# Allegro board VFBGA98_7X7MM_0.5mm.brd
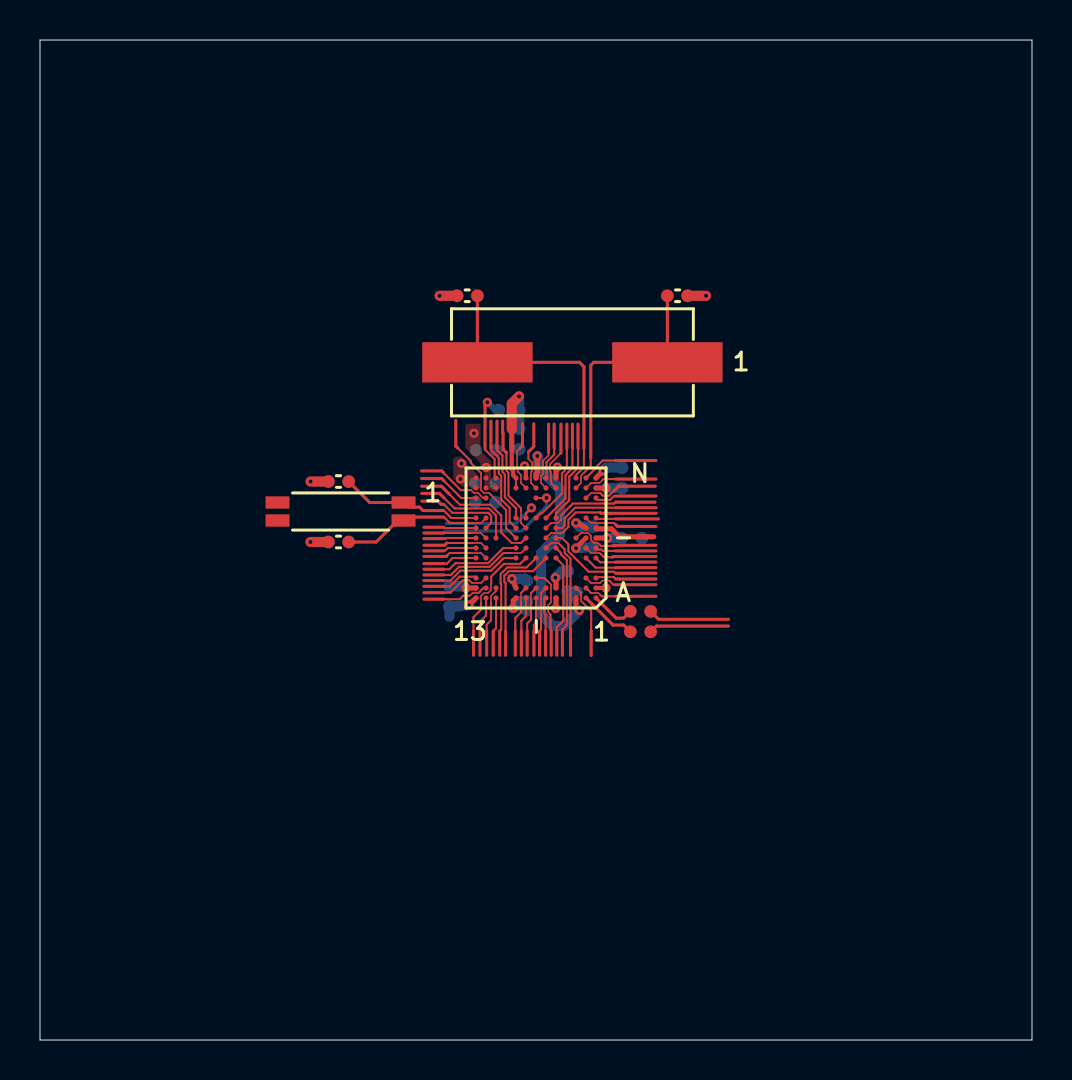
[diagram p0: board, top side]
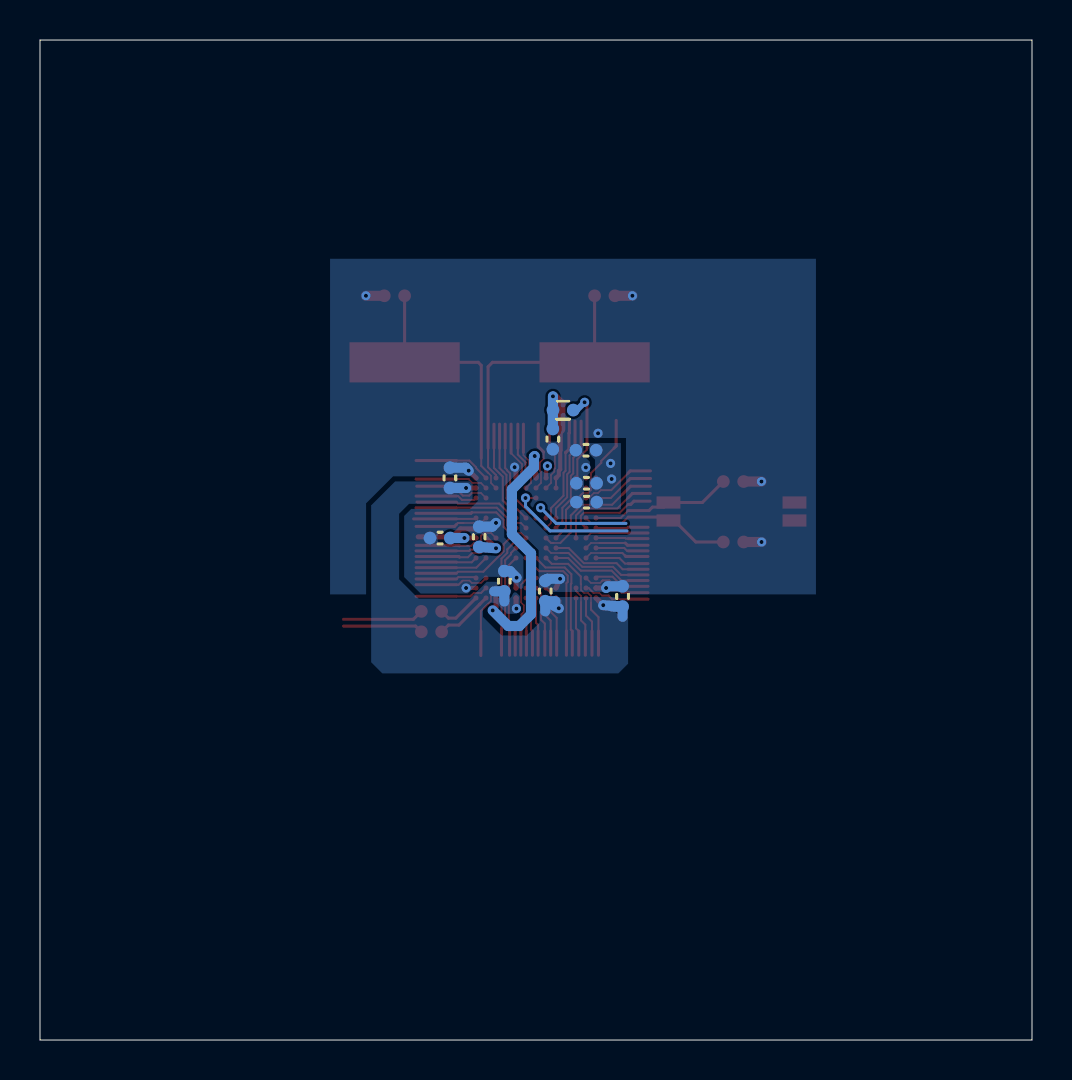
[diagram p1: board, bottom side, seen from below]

Outline 49.6 x 50 mm; copper layers: TOP, BOTTOM. Coordinates in mm from the lower left corner of the outline.
Outline path: 0,50 0,0 49.6,0 49.6,50 0,50

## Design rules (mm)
constraint set DEFAULT: min track width 0.152
net group CSI_LANE: nets P0_13 P0_20 P0_21
net group POWER: nets +3.3V_USB N03445 USB_VBUS VDD3V3_ADC VREFN VREFP

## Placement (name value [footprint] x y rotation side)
C1  22uF  [CC0402_25]  22.28 27.84 0 bottom
C2  0.1UF  [CC0402_25]  22.27 26.89 0 bottom
C3  0.1UF  [CC0402_25]  27.64 25.16 90 bottom
C4  0.1UF  [CC0402_25]  20.47 22.18 90 bottom
C5  4.7UF  [CC0402_25]  24.34 22.45 90 bottom
C6  27PF  [CC0402_25]  21.36 37.21 180 top
C7  0.01UF  [CC0402_25]  29.59 25.1 0 bottom
C8  0.01UF  [CC0402_25]  26.39 22.94 90 bottom
C9  47pF  [CC0402_25]  22.3 29.49 0 bottom
C10  0.1UF  [CC0402_25]  29.1 28.11 90 bottom
C11  27PF  [CC0402_25]  31.88 37.21 0 top
C12  22uF  [CC0402_25]  23.96 30.04 270 bottom
C13  18pF  [CC0402_25]  14.93 27.92 180 top
C14  18pF  [CC0402_25]  14.93 24.9 180 top
L1  33nH  [IND_0402]  23.44 31.5 0 bottom
NOREF  -  []  22.3 28.1 0 top
NOREF#2  -  []  21.3 21.6 90 top
NOREF#3  -  []  -341.81 -256.67 0 top
NOREF#4  -  []  11.88 25.97 90 top
NOREF#5  -  []  25.8 28.1 0 top
NOREF#6  -  []  27.8 28.6 0 top
NOREF#7  -  []  11.88 26.87 0 top
NOREF#8  -  []  21.3 28.6 0 top
NOREF#9  -  []  22.3 28.1 0 top
NOREF#10  -  []  21.8 25.6 90 top
NOREF#11  -  []  276.78 -23.85 0 top
NOREF#12  -  []  91.14 51.78 0 top
NOREF#13  -  []  25.8 28.1 0 top
NOREF#14  -  []  21.3 28.6 0 top
NOREF#15  -  []  21.8 23.1 90 top
NOREF#16  -  []  21.3 21.6 90 top
NOREF#17  -  []  10.89 25.67 90 top
NOREF#18  -  []  21.8 25.6 90 top
NOREF#19  -  []  -58.09 -204.72 0 top
NOREF#20  -  []  278.26 -35.28 90 top
NOREF#21  -  []  -315.77 265.94 0 top
NOREF#22  -  []  21.8 23.1 90 top
NOREF#23  -  []  10.89 27.17 0 top
NOREF#24  -  []  -45.77 -55.12 0 top
R1  33  [RC0402_25]  30.03 20.41 180 top
R2  33  [RC0402_25]  30.03 21.43 180 top
U1  VFBA98_7x7x<1mm_0p5  [BGA98_0P5_7X7X1MM]  24.8 25.1 0 top
Y1  16.000MHZ  [HC49SDLF]  26.62 33.88 180 top
Y2  32.768kHz  [XTAL4_7X1P5_SM]  15.03 26.42 180 top

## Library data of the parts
C1-C14 = CAP_NP
L1 = INDUCTOR
R1 R2 = RES
U1 = VFBA98_7x7x<1mm_0p5
Y1 = XTAL
Y2 = XTAL_14

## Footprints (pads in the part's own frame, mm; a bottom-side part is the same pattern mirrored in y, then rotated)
BGA98_0P5_7X7X1MM
  round 0.254 smd: A1(3,-3) A2(2.5,-3) A3(2,-3) A5(1,-3) A6(0.5,-3) A7(0,-3) A8(-0.5,-3) A9(-1,-3) A11(-2,-3) A12(-2.5,-3) A13(-3,-3) B1(3,-2.5) B2(2.5,-2.5) B3(2,-2.5) B5(1,-2.5) B6(0.5,-2.5) B7(0,-2.5) B8(-0.5,-2.5) B9(-1,-2.5) B11(-2,-2.5) B12(-2.5,-2.5) B13(-3,-2.5) C1(3,-2) C2(2.5,-2) C7(0,-2) C12(-2.5,-2) C13(-3,-2) E1(3,-1) E2(2.5,-1) E5(1,-1) E6(0.5,-1) E7(0,-1) E8(-0.5,-1) E9(-1,-1) E12(-2.5,-1) E13(-3,-1) F1(3,-0.5) F2(2.5,-0.5) F5(1,-0.5) F6(0.5,-0.5) F8(-0.5,-0.5) F9(-1,-0.5) F12(-2.5,-0.5) F13(-3,-0.5) G1(3,0) G2(2.5,0) G3(2,0) G5(1,0) G6(0.5,0) G8(-0.5,0) G9(-1,0) G11(-2,0) G12(-2.5,0) G13(-3,0) H1(3,0.5) H2(2.5,0.5) H5(1,0.5) H6(0.5,0.5) H8(-0.5,0.5) H9(-1,0.5) H12(-2.5,0.5) H13(-3,0.5) J1(3,1) J2(2.5,1) J5(1,1) J6(0.5,1) J7(0,1) J8(-0.5,1) J9(-1,1) J12(-2.5,1) J13(-3,1) L1(3,2) L2(2.5,2) L7(0,2) L12(-2.5,2) L13(-3,2) M1(3,2.5) M2(2.5,2.5) M3(2,2.5) M5(1,2.5) M6(0.5,2.5) M7(0,2.5) M8(-0.5,2.5) M9(-1,2.5) M11(-2,2.5) M12(-2.5,2.5) M13(-3,2.5) N1(3,3) N2(2.5,3) N3(2,3) N5(1,3) N6(0.5,3) N7(0,3) N8(-0.5,3) N9(-1,3) N11(-2,3) N12(-2.5,3) N13(-3,3)
CC0402_25
  round 0.635 smd: 1(-0.508,0) 2(0.508,0)
HC49SDLF
  rect 5.512x2.007 smd: 1(-4.75,0) 2(4.75,0)
IND_0402
  round 0.635 smd: 1(-0.508,0) 2(0.508,0)
RC0402_25
  round 0.635 smd: 1(-0.508,0) 2(0.508,0)
XTAL4_7X1P5_SM
  rect 1.194x0.61 smd: 1(-3.15,-0.45) 2(3.15,-0.45) 3(3.15,0.45) 4(-3.15,0.45)

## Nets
3V3: C4.1 C5.1 C8.1 C10.1 U1.A5 U1.A9 U1.A13 U1.M1
+3.3V_USB: U1.A3 U1.N7
GND: C1.2 C2.2 C3.2 C4.2 C5.2 C6.2 C7.2 C8.2 C9.2 C10.2 C11.2 C12.2 C13.2 C14.2 U1.B1 U1.B5 U1.B9 U1.B13 U1.H2 U1.M11 U1.M12 U1.N1 U1.N5 U1.N12
VBAT: C1.1 C2.1 C9.1 U1.M13 U1.N13
VDD3V3_ADC: C3.1 U1.G2
P0_0: U1.L12
P0_1: U1.F5
P0_2: U1.B11
P0_3: U1.F8
P0_4: U1.E7
P0_5: U1.A7
P0_6: U1.B7
P0_7: U1.G5
P0_8: U1.M2
P0_9: U1.L13
P0_10: U1.F2
P0_11: U1.F1
P0_12: U1.E2
P0_13: U1.C12
P0_14: U1.C13
P0_15: U1.L2
P0_16: U1.J2
P0_17: U1.G3
P0_18: U1.H9
P0_19: U1.E6
P0_20: U1.B12
P0_21: U1.A12
P0_22: U1.E9
P0_23: U1.J1
P0_24: U1.E12
P0_25: U1.A11
P0_26: U1.H12
P0_27: U1.N2
P0_28: U1.F13
P0_29: U1.H8
P0_30: U1.E5
P0_31: U1.L1
P1_0: U1.E1
P1_1: U1.G11
P1_2: U1.G12
P1_3: U1.G13
P1_4: U1.B2
P1_5: U1.M5
P1_6: U1.H5
P1_7: U1.J5
P1_8: U1.A6
P1_9: U1.C1(P1_9)
P1_10: U1.J7
P1_11: U1.G6
P1_12: U1.F12
P1_13: U1.B3
P1_14: U1.L7
P1_15: U1.B6
P1_16: U1.C7
P1_17: U1.J9
P1_18: U1.G9
P1_19: U1.H13
P1_20: U1.C2
P1_21: U1.M7
P1_22: U1.M8
P1_23: U1.J8
P1_24: U1.F6
P1_25: U1.B8
P1_26: U1.E13
P1_27: U1.E8
P1_28: U1.A8
P1_29: U1.G8
P1_30: U1.F9
P1_31: U1.H6
RESET: U1.J6
USB_FS_N: R2.1
USB_FS_P: R1.1
USB_N: U1.N6
USB_P: U1.M6
USB_VBUS: U1.N8
VREFN: U1.H1
VREFP: C7.1 U1.G1
XTAL_RTX_N: C14.1 U1.J12 Y2.4
XTAL_RTX_P: C13.1 U1.J13 Y2.1
N01141: R1.2 U1.A2
N01145: R2.2 U1.A1
N03158: C11.1 U1.M3 Y1.1
N03165: C6.1 U1.N3 Y1.2
N03441: L1.1 U1.N11
N03445: C12.1 L1.2 U1.M9 U1.N9

Pads without a net: Y2 2 3

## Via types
v1: diameter 0.457, hole 0.203, TOP to BOTTOM, 28 vias

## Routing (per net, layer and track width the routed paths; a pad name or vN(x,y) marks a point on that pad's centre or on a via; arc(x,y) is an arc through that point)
3V3: length 7.7
  TOP w0.254: v1(25.78,21.57) 25.8,21.59 25.8,22.1 U1.A5 ; U1.A13 v1(21.44,21.74) ; U1.M1 v1(28.3,27.6) ; v1(23.66,21.58) 23.66,21.96 U1.A9
  BOTTOM w0.508: C5.1 v1(23.66,21.58) ; C5.1 24.34,21.43 ; C5.1 23.83,21.94 ; 20.47,21.16 C4.1 ; C4.1 v1(21.44,21.74) ; C4.1 20.98,21.67 ; C10.1 v1(28.3,27.6) ; 26.89,22.43 C8.1 26.39,21.92
+3.3V_USB: length 13.1
  TOP w0.254: v1(26.96,21.48) 26.8,21.64 U1.A3 ; U1.N7 24.8,28.17 24.8,28.17 24.8,28.31 24.87,28.37 v1(24.87,29.2)
  BOTTOM w0.508: v1(26.96,21.48) 26.19,20.7 25.63,20.7 25.05,21.29 25.05,24.33 26.01,25.29 26.01,27.53 24.9,28.63 24.9,29.16 v1(24.87,29.2)
GND: length 11.6
  TOP w0.203: U1.B1 28.02,22.6 28.02,22.6 v1(28.3,22.6)
  TOP w0.254: U1.B9 v1(23.6,23.06) ; v1(26.8,25.85) 26.85,25.85 U1.H2 ; v1(25.87,28.64) 25.8,28.57 U1.N5 ; v1(21.3,22.6) U1.B13 ; U1.B5 25.8,23.08 v1(25.77,23.11) ; U1.N1 v1(28.17,28.47)
  TOP w0.508: C6.2 v1(19.98,37.21) ; C14.2 v1(13.52,24.9) ; C13.2 v1(13.53,27.92) ; C11.2 v1(33.3,37.21)
  BOTTOM w0.508: v1(25.77,23.11) 26.1,23.45 C8.2 ; v1(28.17,28.47) 28.32,28.62 C10.2 ; C3.2 26.99,25.67 v1(26.8,25.85) ; v1(21.3,22.6) 21.21,22.69 C4.2 ; C5.2 24.23,23.06 v1(23.6,23.06)
  vias: v1(21.7,30.33) v1(22.31,28.63)
VBAT:
  vias: v1(21.07,28.83) v1(21.02,28.05)
VDD3V3_ADC: length 1.6
  TOP w0.229: v1(26.8,24.59) 26.8,24.63 U1.G2
  BOTTOM w0.508: C3.1 v1(26.8,24.59)
P0_0: length 3.8
  TOP w0.081: U1.L12 22.15,27.1 21.9,27.35 21.7,27.35 21.56,27.49
  TOP w0.102: 21.56,27.49 21.04,27.49 20.19,28.34 20.19,28.35
  TOP w0.152: 19.08,28.46 20.09,28.46 20.19,28.35
P0_1: length 5.7
  TOP w0.102: U1.F5 26.05,24.35 26.05,24.28 26.34,23.99 26.34,20.75 26.12,20.53 26.12,20.45
  TOP w0.152: 26.12,20.45 26.12,19.24
P0_2: length 3.6
  TOP w0.081: 22.55,21.89 22.55,22.2 22.71,22.36
  TOP w0.102: 22.33,20.45 22.33,20.77 22.55,20.98 22.55,21.89 ; U1.B11 22.8,22.45 22.71,22.36
  TOP w0.152: 22.33,19.24 22.33,20.45
P0_3: length 5.7
  TOP w0.081: 23.57,24.35 24.05,24.35 U1.F8
  TOP w0.102: 20.19,23.25 20.54,23.25 20.95,23.66 22.48,23.66 23.17,24.35 23.57,24.35
  TOP w0.152: 19.2,23.25 20.19,23.25
P0_4: length 6.2
  TOP w0.102: U1.E7 24.32,23.62 23.36,23.62 23.03,23.29 23.03,22.83 23.06,22.8 23.06,20.52 22.99,20.45
  TOP w0.152: 22.99,19.24 22.99,20.45
P0_5: length 2.9
  TOP w0.102: U1.A7 24.8,20.86 24.69,20.76 24.69,20.45
  TOP w0.152: 24.69,19.24 24.69,20.45
P0_6: length 3.5
  TOP w0.081: 24.55,21.82 24.55,22.35
  TOP w0.102: 24.55,22.35 U1.B7 ; 24.36,20.45 24.36,20.82 24.55,21.02 24.55,21.82
  TOP w0.152: 24.36,19.24 24.36,20.45
P0_7: length 5.9
  TOP w0.102: U1.G5 26.1,25.1 26.42,24.79 26.42,24.43 27.43,23.41 28.7,23.41 28.78,23.34
  TOP w0.152: 30.79,23.34 28.78,23.34
P0_8: length 3.7
  TOP w0.081: 28.16,28.04 27.98,27.85 27.55,27.85 U1.M2
  TOP w0.102: 28.78,28.05 28.17,28.05 28.16,28.04
  TOP w0.152: 28.78,28.05 30.79,28.05
P0_9: length 3.1
  TOP w0.102: 20.19,27.97 21.06,27.1 U1.L13
  TOP w0.152: 19.07,28.07 20.09,28.07 20.19,27.97
P0_10: length 3.7
  TOP w0.081: U1.F2 27.55,24.35 27.99,24.35 28.06,24.28
  TOP w0.102: 28.63,24.14 28.2,24.14 28.06,24.28
  TOP w0.152: 28.63,24.14 28.66,24.18 30.79,24.18
P0_11: length 3.1
  TOP w0.102: U1.F1 27.88,24.52 28.08,24.52 28.14,24.45 28.78,24.45
  TOP w0.152: 30.79,24.45 28.78,24.45
P0_12: length 3.7
  TOP w0.102: 28.78,23.62 27.78,23.62 U1.E2
  TOP w0.152: 30.79,23.62 28.78,23.62
P0_13: length 3.5
  TOP w0.081: 21.5,22.95 21.59,22.85 22.05,22.85 U1.C12
  TOP w0.102: 20.19,22.36 20.52,22.36 21.14,22.98 21.47,22.98 21.5,22.95
  TOP w0.152: 19.2,22.36 20.19,22.36
P0_14: length 2.8
  TOP w0.102: 20.19,22.68 20.49,22.68 20.97,23.16 21.74,23.16 U1.C13
  TOP w0.152: 19.2,22.68 20.19,22.68
P0_15: length 3.8
  TOP w0.081: U1.L2 27.55,27.35 28.01,27.35 28.02,27.34
  TOP w0.102: 28.02,27.34 28.14,27.22 28.46,27.22 28.7,27.47
  TOP w0.152: 28.7,27.47 28.93,27.69 30.76,27.69
P0_16: length 3.7
  TOP w0.081: U1.J2 27.55,25.85 27.9,25.85 28.42,25.85
  TOP w0.102: 28.77,25.78 28.7,25.85 28.42,25.85
  TOP w0.152: 28.77,25.78 28.88,25.68 30.79,25.68
P0_17: length 4.5
  TOP w0.081: 28.05,24.71 27.9,24.85 27.7,24.85 27.55,25 27.55,25.2 27.4,25.35 27.05,25.35 U1.G3
  TOP w0.102: 28.64,24.71 28.05,24.71
  TOP w0.152: 28.64,24.71 28.66,24.73 30.79,24.73
P0_18: length 5.9
  TOP w0.102: U1.H9 23.48,25.92 23.48,26.61 23.06,27.03 23.06,28.21 22.94,28.33 22.94,29.11 22.57,29.48 22.57,29.48 22.54,29.5 22.54,29.59
  TOP w0.152: 22.54,30.94 22.54,29.59
P0_19: length 6.5
  TOP w0.102: 23.28,20.45 23.28,22.84 23.22,22.9 23.22,23.22 23.44,23.44 24.64,23.44 U1.E6
  TOP w0.152: 23.28,19.24 23.28,20.45
P0_20: length 3.3
  TOP w0.081: 21.5,22.22 21.63,22.35 21.92,22.35
  TOP w0.102: U1.B12 22.17,22.6 21.92,22.35 ; 21.5,22.22 21.17,22.22 20.99,22.04 20.19,22.04
  TOP w0.152: 19.2,22.04 20.19,22.04
P0_21: length 3
  TOP w0.102: 22,20.45 22,20.92 22.3,21.22 U1.A12
  TOP w0.152: 22,19.24 22,20.45
P0_22: length 5.1
  TOP w0.102: 20.19,22.97 20.52,22.97 21.02,23.47 22.56,23.47 23.19,24.1 U1.E9
  TOP w0.152: 19.2,22.97 20.19,22.97
P0_23: length 3.1
  TOP w0.102: 28.78,26.06 27.84,26.06 U1.J1
  TOP w0.152: 28.78,26.06 30.92,26.06
P0_24: length 3.3
  TOP w0.081: 21.56,24.35 22.05,24.35 U1.E12
  TOP w0.102: 21.56,24.35 20.48,24.35 20.34,24.21
  TOP w0.152: 19.2,24.18 20.31,24.18 20.34,24.21
P0_25: length 2.9
  TOP w0.102: 22.66,20.45 22.8,20.59 U1.A11
  TOP w0.152: 22.66,19.24 22.66,20.45
P0_26: length 4.5
  TOP w0.102: U1.H12 22.56,25.86 22.56,26.21 22.41,26.36 20.61,26.36 20.19,26.78
  TOP w0.152: 19.09,26.94 19.9,26.94 20.06,26.78 20.19,26.78
P0_27: length 3.9
  TOP w0.102: U1.N2 27.8,28.6 27.8,28.64 28.13,28.97 28.78,28.97
  TOP w0.152: 30.79,28.97 28.78,28.97
P0_28: length 2.7
  TOP w0.102: U1.F13 20.39,24.6 20.24,24.46 20.19,24.46
  TOP w0.152: 19.2,24.46 20.19,24.46
P0_29: length 5.8
  TOP w0.081: 24.05,26.43 24.05,25.85 U1.H8
  TOP w0.102: 23.32,29.37 23.32,28.46 23.42,28.36 23.42,27.21 24.05,26.59 24.05,26.43
  TOP w0.152: 23.13,30.94 23.13,30.36 23.15,30.33 23.15,29.54 23.32,29.37
P0_30: length 5.1
  TOP w0.102: 25.84,20.45 25.84,20.63 26.16,20.95 26.16,23.74 U1.E5
  TOP w0.152: 25.84,19.24 25.84,20.45
P0_31: length 3.1
  TOP w0.102: 28.78,27.2 28.69,27.2 28.5,27 27.9,27 U1.L1
  TOP w0.152: 30.79,27.2 28.78,27.2
P1_0: length 3.1
  TOP w0.102: 28.78,23.9 28.77,23.88 28.02,23.88 U1.E1
  TOP w0.152: 30.79,23.9 28.78,23.9
P1_1: length 5.3
  TOP w0.102: 20.19,27.11 20.73,26.58 22.45,26.58 22.8,26.23 U1.G11
  TOP w0.152: 19.09,27.33 19.98,27.33 20.19,27.11
P1_2: length 3.2
  TOP w0.081: 21.61,25.35 22.05,25.35 U1.G12
  TOP w0.102: 20.19,25.35 21.61,25.35
  TOP w0.152: 19.2,25.35 20.19,25.35
P1_3: length 2.6
  TOP w0.102: U1.G13 20.34,25.1 20.31,25.07 20.19,25.07
  TOP w0.152: 19.2,25.07 20.19,25.07
P1_4: length 3.7
  TOP w0.081: 27.55,22.35 27.7,22.35 27.92,22.35 28.01,22.25
  TOP w0.102: 28.01,22.25 28.08,22.18 28.78,22.18 ; 27.55,22.35 U1.B2
  TOP w0.152: 30.8,22.18 28.78,22.18
P1_5: length 3.5
  TOP w0.081: 25.55,27.99 25.55,28.41 25.5,28.46 25.5,28.49 25.5,28.49 25.5,28.8 26.05,29.34
  TOP w0.102: 25.55,27.99 25.55,27.85 U1.M5
  TOP w0.152: 26.05,30.79 26.05,29.34
P1_6: length 5.6
  TOP w0.102: U1.H5 26.1,25.6 26.24,25.73 26.24,26.09 26.76,26.61 28.78,26.61
  TOP w0.152: 30.8,26.61 28.78,26.61
P1_7: length 5.1
  TOP w0.102: U1.J5 25.8,26.32 26.46,26.97 26.46,27 26.46,27 26.46,28.17 26.9,28.61 26.9,29.59
  TOP w0.152: 26.9,30.79 26.9,29.59
P1_8: length 2.9
  TOP w0.081: U1.A6 25.22,22.02 25.22,21.33 25.28,21.27
  TOP w0.102: 25.28,20.45 25.28,21.27
  TOP w0.152: 25.28,19.24 25.28,20.45
P1_9: length 3.1
  TOP w0.102: U1.C1 27.84,23.14 28.68,23.14 28.78,23.05
  TOP w0.152: 30.79,23.05 28.78,23.05
P1_10: length 5.4
  TOP w0.102: U1.J7 25.04,26.34 25.1,26.34 26.09,27.33 26.09,28.33 26.25,28.48 26.25,28.51 26.34,28.6 26.34,29.59
  TOP w0.152: 26.34,29.59 26.34,30.79
P1_11: length 6.3
  TOP w0.081: U1.G6 25.55,25.35 26.06,25.35
  TOP w0.102: 26.06,25.35 26.11,25.35 26.42,25.66 26.42,26.01 26.78,26.38 28.01,26.38
  TOP w0.152: 30.8,26.33 28.05,26.33 28.01,26.38
P1_12: length 3.3
  TOP w0.081: U1.F12 22.05,24.85 21.63,24.85
  TOP w0.102: 20.34,24.85 21.63,24.85
  TOP w0.152: 19.2,24.74 20.22,24.74 20.34,24.85
P1_13: length 3.7
  TOP w0.081: 27.17,21.83 27.05,21.95 27.05,22.18
  TOP w0.102: 27.17,21.83 27.56,21.45 27.56,20.45 ; U1.B3 27.05,22.35 27.05,22.18
  TOP w0.152: 27.56,19.22 27.56,20.45
P1_14: length 6.5
  TOP w0.102: U1.L7 v1(25.32,27.1)
  BOTTOM w0.152: v1(25.32,27.1) 25.32,26.68 24.1,25.46 20.25,25.46
P1_15: length 3.5
  TOP w0.081: 25.05,21.26 25.05,22.35
  TOP w0.102: 25.05,21.26 25.05,20.52 24.98,20.45 ; 25.05,22.35 U1.B6
  TOP w0.152: 24.98,19.24 24.98,20.45
P1_16: length 4.5
  TOP w0.081: 25.52,21.29 25.41,21.4 25.41,21.74 25.55,21.88 25.55,22.77 25.46,22.87
  TOP w0.102: 25.56,20.45 25.52,20.48 25.52,21.29 ; 25.46,22.87 25.22,23.1 U1.C7
  TOP w0.152: 25.56,19.24 25.56,20.45
P1_17: length 5.2
  TOP w0.102: 22.85,29.59 22.85,29.5 22.87,29.48 22.87,29.48 23.12,29.23 23.12,28.4 23.24,28.28 23.24,27.14 23.8,26.58 U1.J9
  TOP w0.152: 22.85,29.59 22.85,30.94
P1_18: length 7.3
  TOP w0.081: 22.53,27.28 22.45,27.35 22.2,27.35 22.05,27.5 22.05,28.26
  TOP w0.102: 20.9,29.59 21.54,28.95 21.54,28.86 22.05,28.34 22.05,28.26 ; U1.G9 23.3,25.6 23.3,26.5 22.53,27.28
  TOP w0.152: 20.9,29.59 20.79,29.7 20.79,30.98
P1_19: length 2.6
  TOP w0.102: 20.19,25.64 20.23,25.6 U1.H13
  TOP w0.152: 19.2,25.64 20.19,25.64
P1_20: length 3.7
  TOP w0.081: 28.5,22.94 28.46,22.97 28.13,22.97 28.01,22.85 27.55,22.85 U1.C2
  TOP w0.102: 28.5,22.94 28.67,22.77 28.78,22.77
  TOP w0.152: 30.79,22.77 28.78,22.77
P1_21: length 3.5
  TOP w0.081: 24.42,29.06 24.61,28.87 24.61,28.46 24.55,28.41 24.55,27.85 U1.M7
  TOP w0.102: 24.42,29.4 24.42,29.06
  TOP w0.152: 24.69,30.81 24.69,29.67 24.42,29.4
P1_22: length 3.5
  TOP w0.081: 24.01,29.59 23.85,29.43 23.85,28.58 23.88,28.55 23.88,28.42 24.05,28.25 24.05,27.85 U1.M8
  TOP w0.152: 24.01,29.59 24.12,29.7 24.12,30.83
P1_23: length 5.2
  TOP w0.102: v1(24.57,26.61) 24.3,26.34 U1.J8
  BOTTOM w0.152: 20.3,25.83 23.79,25.83 v1(24.57,26.61)
P1_24: length 6.6
  TOP w0.081: 25.92,24.85 25.55,24.85 U1.F6
  TOP w0.102: 25.92,24.85 26.24,24.53 26.24,24.35 26.53,24.06 26.53,20.57
  TOP w0.152: 26.53,19.24 26.53,20.57
P1_25: length 3.6
  TOP w0.081: 24.05,21.88 24.05,22.35
  TOP w0.102: 24.05,22.35 U1.B8 ; 23.77,20.45 23.77,21.11 24.05,21.39 24.05,21.88
  TOP w0.152: 23.77,19.24 23.77,20.45
P1_26: length 2.7
  TOP w0.102: U1.E13 20.63,24.1 20.35,23.82 20.19,23.82
  TOP w0.152: 19.2,23.82 20.19,23.82
P1_27: length 6.5
  TOP w0.081: 22.56,22.79 22.55,22.78 22.55,22.5 22.4,22.35 22.2,22.35 22.05,22.2 22.05,21.87
  TOP w0.102: 21.68,20.45 21.68,21.15 22.05,21.52 22.05,21.87 ; U1.E8 24.01,23.81 23.19,23.81 22.56,23.17 22.56,22.79
  TOP w0.152: 21.68,19.24 21.68,20.45
P1_28: length 3
  TOP w0.102: 24.07,20.45 24.07,20.97 24.3,21.2 U1.A8
  TOP w0.152: 24.07,19.24 24.07,20.45
P1_29: length 7
  TOP w0.081: 23.58,24.85 23.92,24.85
  TOP w0.102: 23.92,24.85 24.05,24.85 U1.G8 ; 20.47,27.29 21,26.76 22.52,26.76 23.06,26.23 23.06,25.38 23.58,24.85
  TOP w0.152: 20.47,27.29 20.07,27.69 19.08,27.69
P1_30: length 5
  TOP w0.102: 20.19,23.54 20.47,23.54 20.77,23.84 22.41,23.84 23.17,24.6 U1.F9
  TOP w0.152: 19.2,23.54 20.19,23.54
P1_31: length 6.1
  TOP w0.081: U1.H6 25.55,25.85 25.9,25.85 26.06,26.01 26.06,26.24
  TOP w0.102: 28.78,26.89 28.71,26.82 26.64,26.82 26.06,26.24
  TOP w0.152: 30.75,26.89 28.78,26.89
RESET: length 5.2
  TOP w0.102: 26.62,29.59 26.62,28.6 26.43,28.41 26.43,28.41 26.28,28.25 26.28,27.08 U1.J6
  TOP w0.152: 26.62,29.59 26.62,30.79
USB_FS_N: length 4.1
  TOP w0.152: R2.1 30.93,21.04 34.42,21.04
USB_FS_P: length 4
  TOP w0.152: 34.42,20.7 30.82,20.7 R1.1
USB_N: length 2.9
  TOP w0.102: 25.71,29.59 25.71,29.27 25.33,28.89 25.33,28.87 25.33,28.87 25.33,28.23 25.3,28.21 U1.N6
  TOP w0.152: 25.71,30.79 25.71,29.59
USB_P: length 3.4
  TOP w0.081: 25.43,29.38 25.43,29.24 25.15,28.96 25.15,28.94 25.15,28.94 25.15,28.31 25.05,28.2 25.05,27.85 U1.M6
  TOP w0.152: 25.43,30.79 25.43,29.38
USB_VBUS: length 0.6
  TOP w0.203: v1(24.23,28.7) 24.23,28.67 24.29,28.61 24.29,28.14 24.29,28.14 24.29,28.11 U1.N8
VREFN: length 3.1
  TOP w0.254: 30.69,25.16 28.97,25.16 28.57,25.56 27.84,25.56 U1.H1
VREFP: length 1.3
  TOP w0.254: U1.G1 v1(28.38,25.1)
  BOTTOM w0.508: C7.1 v1(28.38,25.1)
XTAL_RTX_N: length 7.6
  TOP w0.081: 21.68,25.85 22.05,25.85 U1.J12
  TOP w0.102: 20.19,26.15 20.49,25.85 21.68,25.85
  TOP w0.152: 20.19,26.15 18.35,26.15 Y2.4 17.88,25.97 16.81,24.9 C14.1
XTAL_RTX_P: length 7.1
  TOP w0.102: 20.19,26.47 20.56,26.1 U1.J13
  TOP w0.152: C13.1 16.48,26.87 Y2.1 18.41,26.64 18.98,26.64 19.15,26.47 20.19,26.47
N01141: length 2.9
  TOP w0.152: R1.2 29.18,20.75 28.65,20.75 U1.A2
N01145: length 2.3
  TOP w0.152: U1.A1 28.81,21.09 29.18,21.09 R2.2
N03158: length 13.7
  TOP w0.081: 27.19,28.36 27.05,28.22 27.05,27.85 U1.M3
  TOP w0.102: 27.54,29.1 27.54,28.7 27.19,28.36
  TOP w0.152: 27.54,29.1 27.54,33.73 27.69,33.88 Y1.1 C11.1
N03165: length 14.5
  TOP w0.102: 27.2,29.59 27.2,28.64 26.8,28.25 U1.N3
  TOP w0.152: 27.2,29.59 27.2,33.66 26.97,33.88 Y1.2 C6.1
N03441: length 4.8
  TOP w0.102: 22.25,29.59 22.25,29.52 22.73,29.04 22.73,28.17 U1.N11
  TOP w0.152: v1(22.37,31.89) 22.25,31.77 22.25,29.59
  BOTTOM w0.305: v1(22.37,31.89) 22.76,31.5 22.94,31.5
N03445: length 6.5
  TOP w0.102: U1.M9 U1.N9
  TOP w0.203: 23.59,29.5 23.59,28.53 23.66,28.46 23.66,28.24 U1.N9
  TOP w0.254: 23.59,30.55 23.59,29.5
  TOP w0.508: v1(23.95,32.18) 23.59,31.82 23.59,30.55
  BOTTOM w0.508: C12.1 23.96,31.31 23.95,31.32 L1.2 v1(23.95,32.18)

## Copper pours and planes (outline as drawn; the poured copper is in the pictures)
3V3 on BOTTOM: 20.2,21.91 20.2,18.82 20.68,18.33 32.48,18.33 33.04,18.89 33.04,26.73 31.84,27.93 28.12,27.93 27.97,27.79 27.97,27.03 28.19,26.81 31.14,26.81 31.65,26.31 31.65,23.04 30.67,22.07 28.1,22.07 27.26,22.91 26.32,22.91 25.61,22.2 25.61,21.48 25.78,21.31 26.31,21.31 26.78,21.78 27.22,21.78 27.45,21.55 27.45,21.17 26.52,20.23 25.27,20.23 24.63,20.86 24.63,22.07 24.4,22.3 24.25,22.15 20.42,22.15 20.42,22.14
GND on TOP: 22.02,28.85 22.02,27.52 22.14,27.39 22.88,27.39 22.95,27.46 22.95,27.88 22.86,27.97 22.71,27.97 22.63,28.05 22.63,28.85 22.01,29.48 22.02,29.5 22.02,30.81 21.34,30.81 21.26,30.73 21.26,30.16 21.26,30.16 21.26,29.61
GND on BOTTOM: 10.8,22.28 10.8,39.06 35.1,39.06 35.1,22.28
VBAT on TOP: 21.91,28.31 21.91,27.54 21.8,27.43 21.71,27.43 21.58,27.56 21.09,27.56 20.66,27.99 20.66,29.05 20.77,29.17 21.25,29.17 21.25,28.97
VBAT on BOTTOM: 20.55,26.53 20.55,29.85 22.15,29.85 22.15,29.31 21.85,29.01 21.85,28.26 22.15,27.96 22.15,26.53

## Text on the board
BOTTOM: 5 OF 8 | SECONDARY SIDE
Board Geometry/Soldermask Bottom: 6 OF 8 | SECONDARY SOLDERMASK
Ref Des/Silkscreen Bottom: 7 OF 8 | SECONDARY SILKSCREEN
User.Comments: 1 OF 1 | TEST PROBE | 1/1 | 1
TOP: 4 OF 8 | PRIMARY SIDE
Board Geometry/Soldermask Top: 3 OF 8 | PRIMARY SOLDERMASK
Ref Des/Silkscreen Top: 2 OF 8 | PRIMARY SILKSCREEN
DIMENSION: 8
PASTEMASK_TOP: 1 OF 8 | PASTEMASK TOP
PASTEMASK_BOTTOM: 8 OF 8 | SECONDARY PASTEMASK
User.11: X-NIOBE4-BMS
User.14: VFBA98 7 x 7 x <1mm - pitch 0.5
User.20: FIGURE | SIZE | 8.0 | DRILL CHART: TOP to BOTTOM | ALL UNITS ARE IN MILS | TOLERANCE | +0.0/-8.0 | PLATED | QTY | 27
